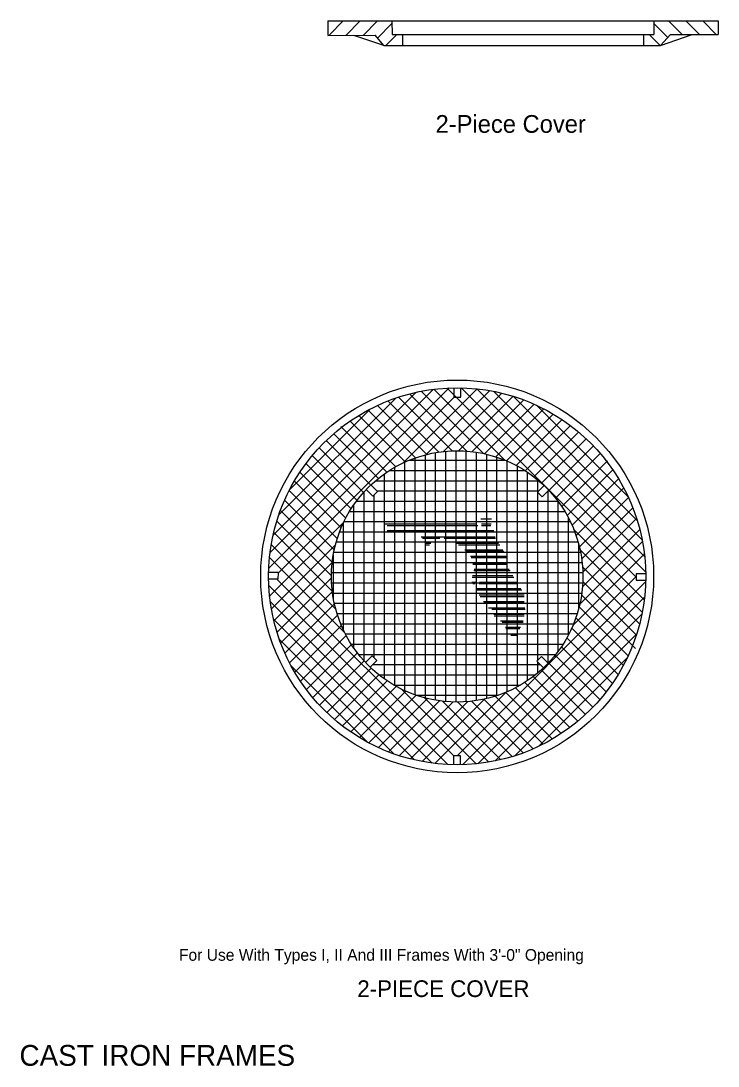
# Model space of a CAD drawing. Extents: x 4851 to 4902, y 9954.5 to 9971.9.
# Drawn here: x 4856.61 to 4861.93, y 9954.52 to 9962.5 of the extents above; entities that cross this region are included whole.
import ezdxf

# ---------------------------------------------------------------- set-up
doc = ezdxf.new("R2010")
doc.units = 0
for name, color, linetype in [('Default', 7, 'Continuous'), ('Dimension', 7, 'Continuous'), ('DSText', 7, 'Continuous'), ('TextMisc', 7, 'Continuous')]:
    doc.layers.add(name, color=color, linetype=linetype)

msp = doc.modelspace()

# ---------------------------------------------------------------- linework, layer by layer
at = {"layer": 'Default'}
for p, q in [((4860.1202, 9958.6982), (4860.2011, 9958.6982)), ((4859.3887, 9958.6597), (4860.088, 9958.6597)), ((4859.4058, 9958.6489), (4860.0975, 9958.6489)), ((4859.4058, 9958.6105), (4860.2192, 9958.6105)), ((4860.126, 9958.6597), (4860.2002, 9958.6597)), ((4860.1265, 9958.6489), (4860.1966, 9958.6489)), ((4859.3968, 9958.5996), (4860.2215, 9958.5996)), ((4859.6642, 9958.5611), (4860.2296, 9958.5611)), ((4859.6741, 9958.5503), (4859.8084, 9958.5503)), ((4859.8419, 9958.5503), (4860.2323, 9958.5503)), ((4859.6935, 9958.5118), (4859.7378, 9958.5118)), ((4859.6976, 9958.501), (4859.7298, 9958.501)), ((4859.9383, 9958.5118), (4860.2563, 9958.5118)), ((4859.951, 9958.501), (4860.2649, 9958.501)), ((4859.998, 9958.4625), (4860.2898, 9958.4625)), ((4860.003, 9958.4516), (4860.297, 9958.4516)), ((4860.0414, 9958.4132), (4860.3156, 9958.4132)), ((4860.0478, 9958.4024), (4860.3169, 9958.4024)), ((4860.06, 9958.3639), (4860.3156, 9958.3639)), ((4860.06, 9958.353), (4860.3169, 9958.353)), ((4860.0672, 9958.3037), (4860.3445, 9958.3037)), ((4860.0686, 9958.3146), (4860.3382, 9958.3146)), ((4860.0509, 9958.2159), (4860.0799, 9958.2159)), ((4860.0555, 9958.2544), (4860.3721, 9958.2544)), ((4860.0577, 9958.2652), (4860.3658, 9958.2652)), ((4860.0609, 9958.2051), (4860.0749, 9958.2051)), ((4860.1079, 9958.2051), (4860.4024, 9958.2051)), ((4860.1106, 9958.2159), (4860.3956, 9958.2159)), ((4860.0885, 9958.1558), (4860.4346, 9958.1558)), ((4860.0921, 9958.1666), (4860.4273, 9958.1666)), ((4860.1084, 9958.1173), (4860.4504, 9958.1173)), ((4860.1165, 9958.1065), (4860.4522, 9958.1065)), ((4860.1423, 9958.068), (4860.4526, 9958.068)), ((4860.1473, 9958.0571), (4860.4522, 9958.0571)), ((4860.1803, 9958.0187), (4860.4571, 9958.0187)), ((4860.2052, 9958.0079), (4860.459, 9958.0079)), ((4860.2197, 9957.9694), (4860.4526, 9957.9694)), ((4860.2233, 9957.9585), (4860.4522, 9957.9585)), ((4860.2712, 9957.9201), (4860.4431, 9957.9201)), ((4860.2844, 9957.9093), (4860.4431, 9957.9093)), ((4860.3102, 9957.8708), (4860.4246, 9957.8708)), ((4860.3106, 9957.8599), (4860.4173, 9957.8599)), ((4860.3355, 9957.8215), (4860.406, 9957.8215)), ((4860.3486, 9957.8106), (4860.3979, 9957.8106))]:
    msp.add_line(p, q, dxfattribs=at)
at = {"layer": 'Dimension'}
for p, q in [((4858.9531, 9962.5016), (4861.9321, 9962.5019)), ((4858.9531, 9962.5016), (4858.9533, 9962.3921)), ((4859.4423, 9962.5017), (4859.4425, 9962.3977)), ((4861.4424, 9962.5019), (4861.4426, 9962.3977)), ((4861.9321, 9962.5019), (4861.9321, 9962.3977)), ((4858.9531, 9962.391), (4859.3152, 9962.3918)), ((4859.379, 9962.3141), (4859.1517, 9962.3914)), ((4859.379, 9962.3141), (4859.3152, 9962.3918)), ((4859.4425, 9962.3977), (4861.4427, 9962.3977)), ((4859.5234, 9962.3977), (4859.5235, 9962.3144)), ((4861.3619, 9962.3977), (4861.362, 9962.3141)), ((4861.4929, 9962.3141), (4861.7336, 9962.3973)), ((4861.4929, 9962.3141), (4861.5691, 9962.397)), ((4861.5691, 9962.397), (4861.9321, 9962.3977)), ((4859.379, 9962.3141), (4859.379, 9962.3141)), ((4859.379, 9962.3141), (4861.4929, 9962.3141)), ((4858.5012, 9958.3208), (4859.8789, 9959.6986)), ((4858.5114, 9958.4414), (4859.7584, 9959.6884)), ((4858.5348, 9958.5752), (4859.6245, 9959.6649)), ((4859.5265, 9959.1255), (4860.0928, 9959.6917)), ((4860.0131, 9959.2164), (4859.5763, 9959.6532)), ((4860.1422, 9959.1976), (4859.6662, 9959.6736)), ((4859.7, 9959.1886), (4860.1894, 9959.6781)), ((4860.3018, 9959.1484), (4859.7615, 9959.6888)), ((4859.8351, 9959.2134), (4860.2807, 9959.659)), ((4861.3076, 9958.2528), (4859.8627, 9959.6978)), ((4859.9182, 9959.6277), (4859.9182, 9959.6997)), ((4859.9689, 9959.6275), (4859.9689, 9959.6996)), ((4861.3796, 9958.2912), (4859.9714, 9959.6995)), ((4861.3722, 9958.409), (4860.0892, 9959.6921)), ((4861.3526, 9958.5389), (4860.219, 9959.6725)), ((4858.5785, 9958.7293), (4859.4705, 9959.6212)), ((4858.5786, 9958.2879), (4859.9182, 9959.6275)), ((4859.7078, 9959.1906), (4859.3328, 9959.5656)), ((4859.7999, 9959.2089), (4859.41, 9959.5988)), ((4859.9008, 9959.2183), (4859.4911, 9959.6281)), ((4859.9182, 9959.6277), (4859.9689, 9959.6275)), ((4859.9511, 9959.2191), (4860.3671, 9959.635)), ((4860.0547, 9959.2123), (4860.4492, 9959.6068)), ((4860.149, 9959.1961), (4860.5274, 9959.5746)), ((4861.3152, 9958.6866), (4860.3668, 9959.6351)), ((4861.246, 9958.8662), (4860.5464, 9959.5659)), ((4858.6614, 9958.9225), (4859.2772, 9959.5383)), ((4859.5441, 9959.1337), (4859.1891, 9959.4887)), ((4859.6229, 9959.1652), (4859.2593, 9959.5289)), ((4860.2357, 9959.1725), (4860.6019, 9959.5387)), ((4860.316, 9959.1425), (4860.6729, 9959.4994)), ((4859.4026, 9959.0545), (4859.053, 9959.4041)), ((4859.4708, 9959.0966), (4859.1222, 9959.4452)), ((4860.3907, 9959.1068), (4860.7406, 9959.4567)), ((4860.4602, 9959.066), (4860.8051, 9959.4109)), ((4859.339, 9959.0077), (4858.9978, 9959.3489)), ((4859.0585, 9959.3986), (4859.0585, 9959.3986)), ((4860.525, 9959.0204), (4860.8666, 9959.362)), ((4859.2801, 9958.9563), (4858.9401, 9959.2962)), ((4860.5851, 9958.9702), (4860.925, 9959.3101)), ((4860.6407, 9958.9155), (4860.9805, 9959.2552)), ((4859.1757, 9958.8399), (4858.8338, 9959.1819)), ((4859.2256, 9958.9003), (4858.8855, 9959.2406)), ((4859.6192, 9957.3544), (4859.6192, 9959.1639)), ((4859.6972, 9957.3304), (4859.6972, 9959.1879)), ((4859.7752, 9957.3134), (4859.7752, 9959.2049)), ((4859.8533, 9957.3031), (4859.8533, 9959.2152)), ((4859.9313, 9957.2992), (4859.9313, 9959.2191)), ((4860.0093, 9957.3016), (4860.0093, 9959.2166)), ((4860.0874, 9957.3105), (4860.0874, 9959.2078)), ((4860.1654, 9957.326), (4860.1654, 9959.1923)), ((4860.2434, 9957.3483), (4860.2434, 9959.17)), ((4860.6918, 9958.8562), (4861.033, 9959.1973)), ((4859.1304, 9958.7748), (4858.7851, 9959.1202)), ((4859.4631, 9957.426), (4859.4631, 9959.0923)), ((4859.5411, 9957.386), (4859.5411, 9959.1323)), ((4859.5729, 9959.1462), (4860.3073, 9959.1462)), ((4860.3214, 9957.3781), (4860.3214, 9959.1402)), ((4860.3995, 9957.4162), (4860.3995, 9959.1021)), ((4860.7384, 9958.7924), (4861.0824, 9959.1364)), ((4861.0823, 9959.1365), (4861.0823, 9959.1365)), ((4861.0824, 9959.1363), (4861.0882, 9959.1421)), ((4858.7396, 9959.0553), (4859.0899, 9958.705)), ((4859.3851, 9957.4759), (4859.3851, 9959.0424)), ((4859.4232, 9959.0681), (4860.457, 9959.0681)), ((4860.4775, 9957.4637), (4860.4775, 9959.0546)), ((4860.7802, 9958.7238), (4861.1287, 9959.0724)), ((4860.8168, 9958.6502), (4861.1719, 9959.0053)), ((4859.0546, 9958.6299), (4858.6971, 9958.9873)), ((4859.2969, 9958.8714), (4859.246, 9958.9223)), ((4859.3329, 9958.9071), (4859.282, 9958.958)), ((4859.3177, 9958.9901), (4860.5625, 9958.9901)), ((4860.5524, 9958.9023), (4860.6033, 9958.9533)), ((4860.5555, 9957.6193), (4860.5555, 9958.9959)), ((4860.848, 9958.571), (4861.2119, 9958.9349)), ((4859.025, 9958.5492), (4858.6581, 9958.916)), ((4859.229, 9957.6142), (4859.229, 9958.9041)), ((4859.3329, 9958.9071), (4859.2969, 9958.8714)), ((4859.307, 9957.6369), (4859.307, 9958.8815)), ((4859.3279, 9958.9121), (4860.5621, 9958.9121)), ((4860.5524, 9958.9023), (4860.588, 9958.8664)), ((4860.588, 9958.8664), (4860.639, 9958.9173)), ((4860.6336, 9957.5966), (4860.6336, 9958.9119)), ((4860.873, 9958.4856), (4861.2484, 9958.861)), ((4858.9862, 9958.3671), (4858.5905, 9958.7627)), ((4859.0018, 9958.462), (4858.6225, 9958.8412)), ((4859.151, 9957.7124), (4859.151, 9958.8058)), ((4859.1713, 9958.834), (4860.7089, 9958.834)), ((4860.7116, 9957.6878), (4860.7116, 9958.8305)), ((4860.8907, 9958.393), (4861.2813, 9958.7836)), ((4859.1187, 9958.756), (4860.7615, 9958.756)), ((4860.7896, 9957.812), (4860.7896, 9958.7062)), ((4860.8996, 9958.2915), (4861.3103, 9958.7022)), ((4858.508, 9958.107), (4859.0738, 9958.6728)), ((4858.9801, 9958.2629), (4858.5626, 9958.6803)), ((4859.0729, 9957.8473), (4859.0729, 9958.671)), ((4859.0763, 9958.678), (4860.8039, 9958.678)), ((4861.3688, 9958.0813), (4860.8294, 9958.6207)), ((4860.8967, 9958.1782), (4861.335, 9958.6165)), ((4858.9868, 9958.1458), (4858.5391, 9958.5935)), ((4859.0426, 9958.5999), (4860.8376, 9958.5999)), ((4860.8765, 9958.0477), (4861.355, 9958.5262)), ((4859.0133, 9958.009), (4858.5204, 9958.5019)), ((4858.5217, 9958.0103), (4859.0106, 9958.4993)), ((4858.998, 9958.4439), (4860.8822, 9958.4439)), ((4859.0168, 9958.5219), (4860.8634, 9958.5219)), ((4860.8677, 9958.0117), (4860.8677, 9958.5066)), ((4861.3536, 9957.9861), (4860.8786, 9958.4611)), ((4859.0808, 9957.8312), (4858.5072, 9958.4047)), ((4858.5408, 9957.9191), (4858.9859, 9958.3642)), ((4858.9861, 9958.3658), (4860.8941, 9958.3658)), ((4858.9949, 9958.0911), (4858.9949, 9958.4271)), ((4860.8242, 9957.885), (4861.3697, 9958.4306)), ((4858.5722, 9958.2879), (4858.5002, 9958.2879)), ((4858.5722, 9958.2879), (4858.5721, 9958.2373)), ((4858.9805, 9958.2878), (4860.8997, 9958.2878)), ((4861.3332, 9957.8961), (4860.8973, 9958.332)), ((4858.5721, 9958.2373), (4858.5001, 9958.2373)), ((4859.9113, 9956.8905), (4858.5643, 9958.2373)), ((4858.5647, 9957.8326), (4858.9802, 9958.2481)), ((4858.9814, 9958.2098), (4860.8988, 9958.2098)), ((4859.9416, 9956.8921), (4861.3076, 9958.2581)), ((4859.9803, 9956.8204), (4861.3793, 9958.2195)), ((4861.3081, 9957.8109), (4860.8993, 9958.2197)), ((4861.3077, 9958.281), (4861.3075, 9958.2304)), ((4861.3075, 9958.2304), (4861.3796, 9958.2304)), ((4861.3077, 9958.281), (4861.3797, 9958.281)), ((4859.8698, 9956.8216), (4858.5016, 9958.1896)), ((4858.593, 9957.7505), (4858.987, 9958.1446)), ((4858.9886, 9958.1317), (4860.8916, 9958.1317)), ((4859.7484, 9956.8327), (4858.5127, 9958.0681)), ((4858.6252, 9957.6724), (4859.0031, 9958.0503)), ((4859.0023, 9958.0537), (4860.8779, 9958.0537)), ((4860.0989, 9956.8287), (4861.3711, 9958.1009)), ((4861.3008, 9957.7078), (4860.8898, 9958.1189)), ((4859.0229, 9957.9757), (4860.8573, 9957.9757)), ((4860.2299, 9956.8494), (4861.3504, 9957.9698)), ((4861.2456, 9957.6527), (4860.8716, 9958.0268)), ((4861.3536, 9957.9861), (4861.3536, 9957.9861)), ((4859.6133, 9956.8574), (4858.5375, 9957.933)), ((4858.6611, 9957.5979), (4859.0267, 9957.9636)), ((4859.0508, 9957.8977), (4860.8294, 9957.8977)), ((4861.2088, 9957.5791), (4860.8462, 9957.9418)), ((4858.7004, 9957.5269), (4859.0567, 9957.8832)), ((4858.743, 9957.4592), (4859.0924, 9957.8086)), ((4859.0866, 9957.8196), (4860.7936, 9957.8196)), ((4860.3795, 9956.8886), (4861.3111, 9957.8202)), ((4861.1686, 9957.509), (4860.8146, 9957.863)), ((4859.4571, 9956.9032), (4858.5833, 9957.7769)), ((4858.7888, 9957.3946), (4859.1332, 9957.739)), ((4859.1316, 9957.7416), (4860.7487, 9957.7416)), ((4861.1251, 9957.4421), (4860.7775, 9957.7897)), ((4861.2788, 9957.7298), (4861.2788, 9957.7298)), ((4858.8377, 9957.3331), (4859.1788, 9957.6743)), ((4859.1872, 9957.6636), (4860.693, 9957.6636)), ((4859.2922, 9957.6519), (4859.2412, 9957.601)), ((4859.3278, 9957.6159), (4859.2922, 9957.6519)), ((4860.5833, 9957.6469), (4860.5473, 9957.6112)), ((4860.5833, 9957.6469), (4860.6342, 9957.5959)), ((4861.0288, 9957.3177), (4860.6886, 9957.658)), ((4861.0785, 9957.3783), (4860.7354, 9957.7215)), ((4859.2589, 9956.9911), (4858.6712, 9957.5787)), ((4858.8896, 9957.2747), (4859.2291, 9957.6141)), ((4859.3278, 9957.6159), (4859.2769, 9957.565)), ((4859.2974, 9957.5855), (4860.573, 9957.5855)), ((4860.5473, 9957.6112), (4860.5983, 9957.5603)), ((4860.5555, 9957.5224), (4860.5555, 9957.603)), ((4860.5628, 9956.9616), (4861.2382, 9957.6369)), ((4860.9762, 9957.26), (4860.6371, 9957.599)), ((4858.9445, 9957.2193), (4859.2838, 9957.5585)), ((4859.0024, 9957.1668), (4859.343, 9957.5074)), ((4859.3429, 9957.5075), (4860.5373, 9957.5075)), ((4860.8618, 9957.1536), (4860.5208, 9957.4947)), ((4860.9205, 9957.2053), (4860.5812, 9957.5446)), ((4859.0634, 9957.1173), (4859.4068, 9957.4609)), ((4859.1273, 9957.071), (4859.4754, 9957.4191)), ((4859.4571, 9957.4295), (4860.4231, 9957.4295)), ((4860.7353, 9957.0595), (4860.3859, 9957.4089)), ((4860.8001, 9957.105), (4860.4557, 9957.4494)), ((4859.1945, 9957.0278), (4859.5491, 9957.3824)), ((4859.2649, 9956.9879), (4859.6282, 9957.3512)), ((4859.3387, 9956.9514), (4859.7136, 9957.3262)), ((4860.0849, 9956.8272), (4859.5123, 9957.3997)), ((4859.6276, 9957.3514), (4860.2526, 9957.3514)), ((4860.1821, 9956.8404), (4859.6902, 9957.3323)), ((4859.7692, 9956.83), (4860.3142, 9957.375)), ((4860.5961, 9956.9781), (4860.2301, 9957.344)), ((4860.6674, 9957.0171), (4860.3109, 9957.3736)), ((4859.4162, 9956.9185), (4859.8062, 9957.3085)), ((4859.4976, 9956.8895), (4859.9077, 9957.2997)), ((4859.5832, 9956.8647), (4860.021, 9957.3026)), ((4859.6735, 9956.8447), (4860.1515, 9957.3227)), ((4860.2737, 9956.8591), (4859.8269, 9957.3058)), ((4860.3605, 9956.8827), (4859.944, 9957.2991)), ((4860.443, 9956.9106), (4860.0482, 9957.3053)), ((4860.5214, 9956.9425), (4860.143, 9957.3208)), ((4859.9113, 9956.8922), (4859.9113, 9956.8202)), ((4859.9113, 9956.8922), (4859.962, 9956.8921)), ((4859.962, 9956.8921), (4859.962, 9956.82))]:
    msp.add_line(p, q, dxfattribs=at)
for centre, radius in [((4859.9401, 9958.2591), 1.5), ((4859.9399, 9958.2599), 1.44), ((4859.9401, 9958.2591), 0.96)]:
    msp.add_circle(centre, radius, dxfattribs=at)
at = {"layer": 'TextMisc'}
for points in [[(4858.9644, 9962.3966), (4859.0695, 9962.5017)], [(4859.0901, 9962.3913), (4859.2005, 9962.5017)], [(4859.2213, 9962.3916), (4859.3314, 9962.5017)], [(4859.332, 9962.3713), (4859.4424, 9962.4816)], [(4861.5492, 9962.3753), (4861.4428, 9962.4816)], [(4861.6583, 9962.3972), (4861.5538, 9962.5017)], [(4861.789, 9962.3974), (4861.6847, 9962.5017)], [(4861.9208, 9962.3966), (4861.8157, 9962.5017)], [(4859.3964, 9962.3142), (4859.4799, 9962.3977)], [(4861.4888, 9962.3142), (4861.4053, 9962.3977)]]:
    msp.add_lwpolyline(points, dxfattribs=at)

# ---------------------------------------------------------------- texts
at = {"layer": 'DSText'}
for s, height, p in [('2-Piece Cover', 0.135375, (4859.7753, 9961.6473)), ('For Use With Types I, II And III Frames With 3\'-0" Opening', 0.089115, (4857.8159, 9955.3234)), ('2-PIECE COVER', 0.127308, (4859.1775, 9955.0465)), ('CAST IRON FRAMES', 0.159135, (4856.5985, 9954.5211))]:
    msp.add_text(s, height=height, dxfattribs=at).set_placement(p)

doc.saveas('drawing.dxf')
